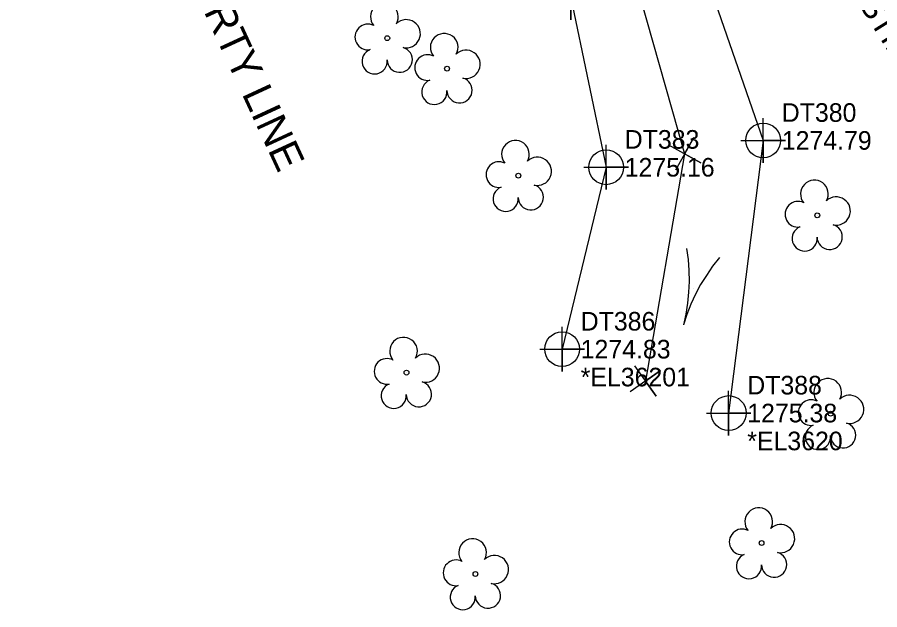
# Model space of a CAD drawing. Extents: x 1393723 to 1394549, y 957573 to 958412.
# Drawn here: x 1394136.3 to 1394252.2, y 957882.1 to 957961.8 of the extents above; entities that cross this region are included whole.
import ezdxf

# ---------------------------------------------------------------- set-up
doc = ezdxf.new("R2010")
doc.units = 0
for name, color, linetype in [('Exist Hydro Jurisdictional Stream or Body of Water', 7, 'Continuous'), ('Exist Hydro Stream Flow Arrow CELL', 7, 'Continuous'), ('Exist Hydro Stream or Body of Water Cogo Comment', 7, 'Continuous'), ('Exist Hydro Stream or Body of Water Cogo Elevation', 7, 'Continuous'), ('Exist Hydro Stream or Body of Water Cogo Number', 7, 'Continuous'), ('Exist Hydro Stream or Body of Water Cogo Point CELL', 7, 'Continuous'), ('Exist Property Corner CELL', 7, 'Continuous'), ('Exist Property Line', 7, 'Continuous'), ('Exist Property Line Text', 7, 'Continuous'), ('Exist Right of Way Line Text', 7, 'Continuous'), ('Exist Roads EOP', 7, 'Continuous'), ('Exist Vegetation Tree CELL', 7, 'Continuous')]:
    doc.layers.add(name, color=color, linetype=linetype)

msp = doc.modelspace()

# ---------------------------------------------------------------- linework, layer by layer
at = {"layer": 'Exist Hydro Jurisdictional Stream or Body of Water'}
for points in [[(1394193.9, 958099.87), (1394177.23, 958076.17), (1394160.33, 958063.43), (1394156.48, 958036.02), (1394151.88, 958011.68), (1394172.23, 957982.06), (1394181.02, 957978.48), (1394196.97, 957983.17), (1394210.71, 957964.43), (1394215.47, 957941.6), (1394209.55, 957917.15)], [(1394208.46, 958075.88), (1394187.58, 958060.01), (1394178.19, 958051.33), (1394177.82, 958039.4), (1394183.63, 958020.31), (1394189.49, 958000.95), (1394211.93, 957995.78), (1394226.78, 957973.54), (1394236.58, 957945.21), (1394231.94, 957908.56)]]:
    msp.add_lwpolyline(points, dxfattribs=at)
at = {"layer": 'Exist Hydro Stream Flow Arrow CELL'}
msp.add_line((1394227.17, 957925.24), (1394227.17, 957925.24), dxfattribs=at)
for points in [[(1394226.28, 957930.66), (1394226.51, 957929.21), (1394226.58, 957927.72), (1394226.63, 957926.24), (1394226.56, 957924.79), (1394226.4, 957923.32), (1394226.17, 957921.84), (1394225.86, 957920.41)], [(1394230.7, 957929.46), (1394229.77, 957928.32), (1394228.94, 957927.07), (1394228.15, 957925.82), (1394227.48, 957924.54), (1394226.86, 957923.2), (1394226.31, 957921.8), (1394225.86, 957920.41)]]:
    msp.add_lwpolyline(points, dxfattribs=at)
at = {"layer": 'Exist Hydro Stream or Body of Water Cogo Point CELL'}
for points in [[(1394207.71, 957964.43), (1394213.71, 957964.43), (1394210.71, 957964.43), (1394210.71, 957961.43), (1394210.71, 957967.43)], [(1394233.58, 957945.21), (1394239.58, 957945.21), (1394236.58, 957945.21), (1394236.58, 957942.21), (1394236.58, 957948.21)], [(1394212.47, 957941.6), (1394218.47, 957941.6), (1394215.47, 957941.6), (1394215.47, 957938.6), (1394215.47, 957944.6)], [(1394206.55, 957917.15), (1394212.55, 957917.15), (1394209.55, 957917.15), (1394209.55, 957914.15), (1394209.55, 957920.15)], [(1394228.94, 957908.56), (1394234.94, 957908.56), (1394231.94, 957908.56), (1394231.94, 957905.56), (1394231.94, 957911.56)]]:
    msp.add_lwpolyline(points, dxfattribs=at)
for centre in [(1394236.58, 957945.21), (1394215.47, 957941.6), (1394209.55, 957917.15), (1394231.94, 957908.56)]:
    msp.add_circle(centre, 2.34, dxfattribs=at)
at = {"layer": 'Exist Property Corner CELL'}
for p, q in [((1394226.02, 957943.4), (1394226.02, 957943.4)), ((1394220.74, 957912.86), (1394220.74, 957912.86))]:
    msp.add_line(p, q, dxfattribs=at)
for points in [[(1394223.84, 957944.62), (1394228.21, 957942.19), (1394226.02, 957943.4), (1394227.24, 957945.59), (1394224.81, 957941.22)], [(1394219.3, 957914.9), (1394222.19, 957910.81), (1394220.74, 957912.86), (1394222.79, 957914.3), (1394218.7, 957911.42)]]:
    msp.add_lwpolyline(points, dxfattribs=at)
at = {"layer": 'Exist Property Line'}
for p, q in [((1394218.74, 957968.99), (1394226.02, 957943.4)), ((1394226.02, 957943.4), (1394220.74, 957912.86))]:
    msp.add_line(p, q, dxfattribs=at)
at = {"layer": 'Exist Roads EOP'}
for points in [[(1394231.47, 958077.14), (1394252.98, 958042.26), (1394277.17, 958002.55), (1394302.35, 957962.17), (1394325.75, 957924.49)], [(1394215.84, 958067.9), (1394237.36, 958032.16), (1394261.7, 957991.75), (1394286.48, 957951.93), (1394310.18, 957914.04)]]:
    msp.add_spline(points, degree=3, dxfattribs=at)
at = {"layer": 'Exist Vegetation Tree CELL'}
for p, q in [((1394186.05, 957958.96), (1394186.05, 957958.96)), ((1394194.09, 957954.85), (1394194.09, 957954.85)), ((1394203.67, 957940.47), (1394203.67, 957940.47)), ((1394243.85, 957935.14), (1394243.85, 957935.14)), ((1394188.63, 957914), (1394188.63, 957914)), ((1394245.65, 957908.47), (1394245.65, 957908.47)), ((1394236.37, 957891.09), (1394236.37, 957891.09)), ((1394197.9, 957886.93), (1394197.9, 957886.93))]:
    msp.add_line(p, q, dxfattribs=at)
for centre in [(1394186.05, 957958.96), (1394194.09, 957954.85), (1394203.67, 957940.47), (1394243.85, 957935.14), (1394188.63, 957914), (1394245.65, 957908.47), (1394236.37, 957891.09), (1394197.9, 957886.93)]:
    msp.add_circle(centre, 0.326, dxfattribs=at)
for centre, radius, start, end in [((1394185.66, 957961.83), 1.86, 330.1651, 219.7134), ((1394183.44, 957959.11), 1.73, 62.6636, 279.3457), ((1394188.6, 957959.55), 1.9, 257.1011, 134.1999), ((1394193.7, 957957.72), 1.86, 330.1651, 219.7134), ((1394184.35, 957955.84), 1.69, 111.5671, 6.231), ((1394187.72, 957956.06), 1.7, 181.2822, 74.56), ((1394196.64, 957955.44), 1.9, 257.1011, 134.1999), ((1394191.48, 957955), 1.73, 62.6636, 279.3457), ((1394192.38, 957951.73), 1.69, 111.5671, 6.231), ((1394195.76, 957951.95), 1.7, 181.2822, 74.56), ((1394203.28, 957943.34), 1.86, 330.1651, 219.7134), ((1394201.06, 957940.62), 1.73, 62.6636, 279.3457), ((1394206.22, 957941.06), 1.9, 257.1011, 134.1999), ((1394243.47, 957938.01), 1.86, 330.1651, 219.7134), ((1394201.96, 957937.35), 1.69, 111.5671, 6.231), ((1394205.34, 957937.57), 1.7, 181.2822, 74.56), ((1394246.4, 957935.72), 1.9, 257.1011, 134.1999), ((1394241.25, 957935.29), 1.73, 62.6636, 279.3457), ((1394242.15, 957932.02), 1.69, 111.5671, 6.231), ((1394245.52, 957932.24), 1.7, 181.2822, 74.56), ((1394188.24, 957916.88), 1.86, 330.1651, 219.7134), ((1394186.02, 957914.16), 1.73, 62.6636, 279.3457), ((1394191.17, 957914.59), 1.9, 257.1011, 134.1999), ((1394245.26, 957911.34), 1.86, 330.1651, 219.7134), ((1394186.92, 957910.88), 1.69, 111.5671, 6.231), ((1394190.3, 957911.1), 1.7, 181.2822, 74.56), ((1394248.2, 957909.06), 1.9, 257.1011, 134.1999), ((1394243.04, 957908.62), 1.73, 62.6636, 279.3457), ((1394243.94, 957905.35), 1.69, 111.5671, 6.231), ((1394247.32, 957905.57), 1.7, 181.2822, 74.56), ((1394235.98, 957893.96), 1.86, 330.1651, 219.7134), ((1394238.92, 957891.68), 1.9, 257.1011, 134.1999), ((1394233.76, 957891.24), 1.73, 62.6636, 279.3457), ((1394197.52, 957889.8), 1.86, 330.1651, 219.7134), ((1394195.3, 957887.08), 1.73, 62.6636, 279.3457), ((1394200.45, 957887.52), 1.9, 257.1011, 134.1999), ((1394234.66, 957887.97), 1.69, 111.5671, 6.231), ((1394238.04, 957888.19), 1.7, 181.2822, 74.56), ((1394196.2, 957883.81), 1.69, 111.5671, 6.231), ((1394199.58, 957884.03), 1.7, 181.2822, 74.56)]:
    msp.add_arc(centre, radius, start, end, dxfattribs=at)

# ---------------------------------------------------------------- texts
at = {"layer": 'Exist Hydro Stream or Body of Water Cogo Comment'}
for s, p in [('*EL36201', (1394212.05, 957912.15)), ('*EL3620', (1394234.44, 957903.56))]:
    msp.add_text(s, height=2.5, dxfattribs=at).set_placement(p)
at = {"layer": 'Exist Hydro Stream or Body of Water Cogo Elevation'}
for s, p in [('1274.79', (1394239.08, 957943.96)), ('1275.16', (1394217.97, 957940.35)), ('1274.83', (1394212.05, 957915.9)), ('1275.38', (1394234.44, 957907.31))]:
    msp.add_text(s, height=2.5, dxfattribs=at).set_placement(p)
at = {"layer": 'Exist Hydro Stream or Body of Water Cogo Number'}
for s, p in [('DT380', (1394239.08, 957947.71)), ('DT383', (1394217.97, 957944.1)), ('DT386', (1394212.05, 957919.65)), ('DT388', (1394234.44, 957911.06))]:
    msp.add_text(s, height=2.5, dxfattribs=at).set_placement(p)
at = {"layer": 'Exist Property Line Text'}
msp.add_text('CENTERLINE OF CREEK = PROPERTY LINE', height=4, rotation=294.7971, dxfattribs=at).set_placement((1394124.63, 958042.03))
at = {"layer": 'Exist Right of Way Line Text'}
msp.add_text('EXISTING R/W', height=3.2, rotation=301.917, dxfattribs=at).set_placement((1394245.72, 957969.4))

doc.saveas('drawing.dxf')
